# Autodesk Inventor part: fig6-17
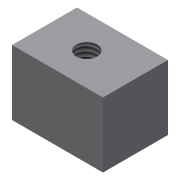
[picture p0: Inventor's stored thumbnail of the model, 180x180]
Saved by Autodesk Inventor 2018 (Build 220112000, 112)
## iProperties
Created: 2009-09
Part Number: fig6-17
Document SubType Name: Modeling
Designer: Sham
Density: 1 g/cm^3
Material: Generic
Appearance: Default
Author: Sham
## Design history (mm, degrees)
sketch "Sketch1"
  geometry: L1 (-28, 20)-(0, 20); L2 (0, 20)-(0, 0); L3 (0, 0)-(-28, 0); L4 (-28, 0)-(-28, 20)
  constraints: 8 end point, 2 parallel, 1 horizontal, 1 perpendicular
extrude "Extrusion1" new body sketch "Sketch1" distance "d0" = 20; taper "d1" = 0 deg
hole "Hole1" diameter "d4" = 6.401; stored, may be unused: countersink angle "d8" = 90 deg, drill point angle "d10" = 118 deg; dims "d2" = 10, "d3" = 15, "d5" = 6, "d6" = 12, "d7" = 3, "d9" = 15
body "Solid1"
